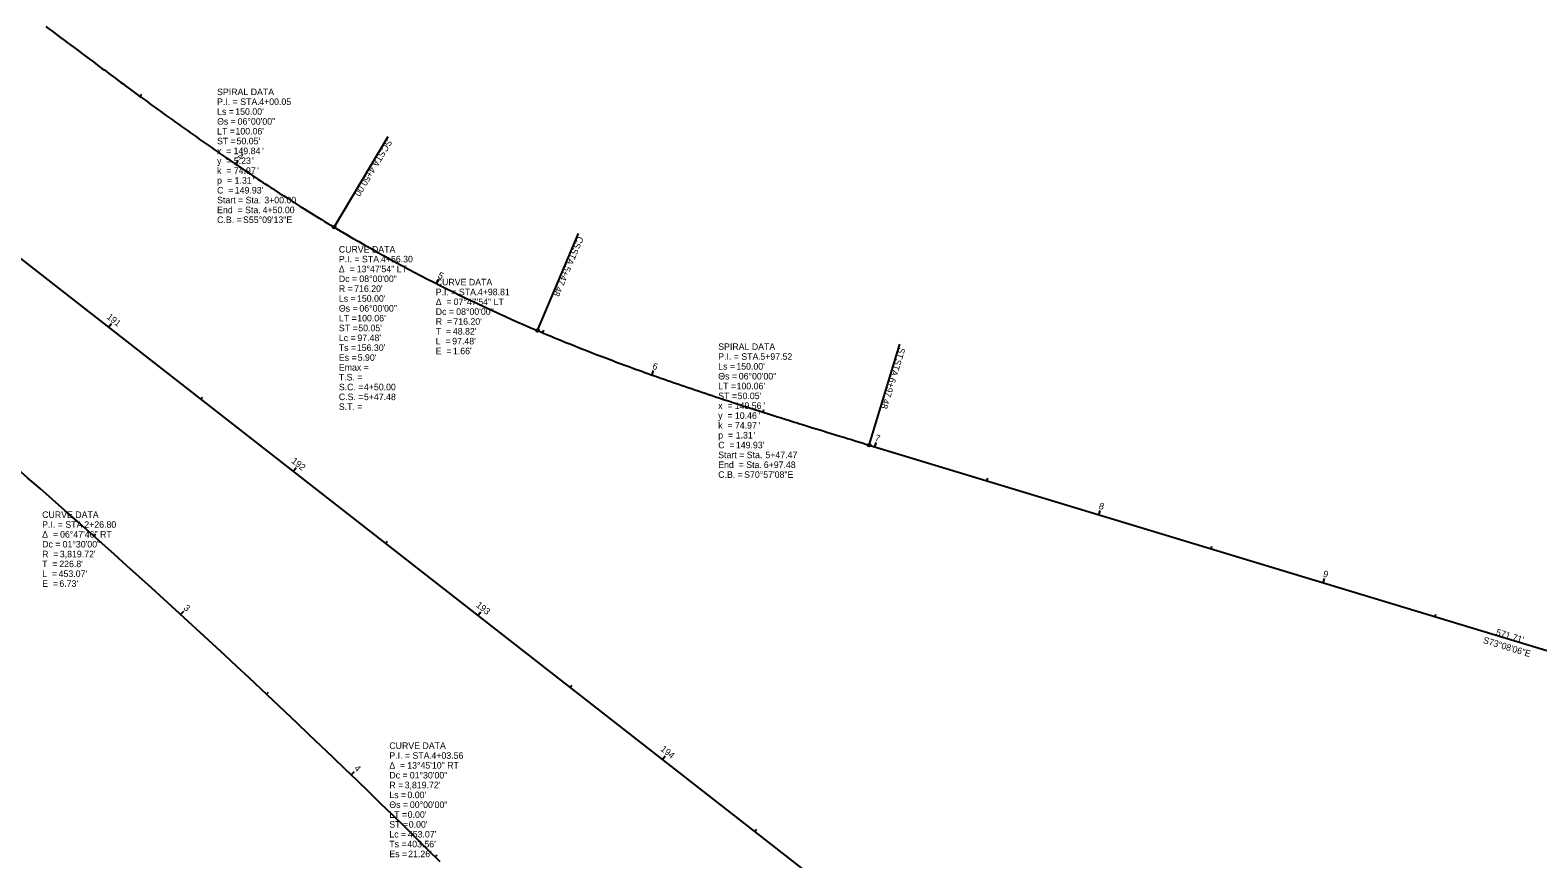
# Model space of a CAD drawing. Extents: x 1323137 to 1326838, y 458936 to 461644.
# Drawn here: x 1324445 to 1325088, y 460335 to 460688 of the extents above; entities that cross this region are included whole.
import ezdxf

# ---------------------------------------------------------------- set-up
doc = ezdxf.new("R2010")
doc.units = 0
for name, color, linetype in [('_CIVIL_CONSTRUCTION', 7, 'Continuous'), ('CM_Corridor_Final', 7, 'Continuous'), ('CM_Corridor_Range_Final', 7, 'Continuous'), ('Default', 7, 'Continuous'), ('DR_P_Ditch', 7, 'Continuous'), ('MD_P_Surface_Asphalt_Concrete_Intermediate_Course', 7, 'Continuous'), ('RD_P_GR_Rt', 7, 'Continuous'), ('SG_P_Wiring', 7, 'Continuous'), ('SN_P_Signs', 7, 'Continuous'), ('SN_X_Public', 7, 'Continuous'), ('UT_P_Electric_Cells', 7, 'Continuous'), ('UT_X_Electric_Cells', 7, 'Continuous')]:
    doc.layers.add(name, color=color, linetype=linetype)

msp = doc.modelspace()

# ---------------------------------------------------------------- linework, layer by layer
at = {"layer": '_CIVIL_CONSTRUCTION'}
for p, q in [((1324574.35, 460604.34), (1324597.43, 460642.98)), ((1324661.18, 460560.2), (1324678.8, 460601.61)), ((1324802.88, 460511.24), (1324815.94, 460554.31))]:
    msp.add_line(p, q, dxfattribs=at)
for centre in [(1324574.35, 460604.34), (1324661.18, 460560.2), (1324802.88, 460511.24)]:
    msp.add_circle(centre, 0.6, dxfattribs=at)
at = {"layer": 'CM_Corridor_Range_Final'}
for p, q in [((1324491.44, 460660.18), (1324492.15, 460661.14)), ((1324532.25, 460631.29), (1324533.37, 460632.95)), ((1324574.36, 460604.34), (1324574.97, 460605.37)), ((1324618.14, 460580.22), (1324619.05, 460582.01)), ((1324478.04, 460561.59), (1324479.27, 460563.17)), ((1324663.5, 460559.22), (1324663.97, 460560.32)), ((1324710.14, 460541.22), (1324710.81, 460543.1)), ((1324517.46, 460530.84), (1324518.2, 460531.78)), ((1324757.56, 460525.35), (1324757.92, 460526.49)), ((1324805.3, 460510.51), (1324805.88, 460512.42)), ((1324556.89, 460500.08), (1324558.12, 460501.66)), ((1324853.15, 460496), (1324853.5, 460497.15)), ((1324901, 460481.5), (1324901.58, 460483.41)), ((1324471.7, 460472.46), (1324472.49, 460473.35)), ((1324596.31, 460469.33), (1324597.05, 460470.28)), ((1324948.85, 460466.99), (1324949.2, 460468.14)), ((1324996.7, 460452.48), (1324997.28, 460454.4)), ((1324508.81, 460438.95), (1324510.16, 460440.42)), ((1324635.73, 460438.58), (1324636.96, 460440.15)), ((1325044.55, 460437.98), (1325044.89, 460439.13)), ((1324545.47, 460404.96), (1324546.29, 460405.83)), ((1324675.16, 460407.82), (1324675.89, 460408.77)), ((1324714.58, 460377.07), (1324715.81, 460378.65)), ((1324581.69, 460370.49), (1324583.08, 460371.93)), ((1324754, 460346.32), (1324754.74, 460347.26)), ((1324617.46, 460335.55), (1324618.3, 460336.4))]:
    msp.add_line(p, q, dxfattribs=at)
at = {"layer": 'Default'}
msp.add_line((1323137.63, 461607.2), (1324879.49, 460248.43), dxfattribs=at)
msp.add_arc((1324941.57, 461219.23), 716.2, 239.15381, 246.95218, dxfattribs=at)
msp.add_open_spline([(1324451.31, 460690.01), (1324454.64, 460687.51), (1324461.31, 460682.51), (1324474.66, 460672.54), (1324491.41, 460660.14), (1324511.67, 460645.5), (1324532.19, 460631.21), (1324549.56, 460619.71), (1324563.66, 460610.81), (1324570.77, 460606.48), (1324574.35, 460604.34)], degree=3, dxfattribs=at)
at = {"layer": 'MD_P_Surface_Asphalt_Concrete_Intermediate_Course'}
for p, q in [((1324574.35, 460604.34), (1324597.43, 460642.98)), ((1324661.18, 460560.2), (1324678.8, 460601.61)), ((1324802.88, 460511.24), (1324815.94, 460554.31))]:
    msp.add_line(p, q, dxfattribs=at)
for centre in [(1324574.35, 460604.34), (1324661.18, 460560.2), (1324802.88, 460511.24)]:
    msp.add_circle(centre, 0.6, dxfattribs=at)
at = {"layer": 'SN_P_Signs'}
for p, q in [((1323137.63, 461607.2), (1324879.49, 460248.43)), ((1324802.88, 460511.24), (1325350.01, 460345.38))]:
    msp.add_line(p, q, dxfattribs=at)
for centre, radius, start, end in [((1321930.37, 457620.81), 3819.72, 45.2472, 52.04331), ((1324941.57, 461219.23), 716.2, 239.15381, 246.95218)]:
    msp.add_arc(centre, radius, start, end, dxfattribs=at)
for points in [[(1324451.31, 460690.01), (1324454.64, 460687.51), (1324461.31, 460682.51), (1324474.66, 460672.54), (1324491.41, 460660.14), (1324511.67, 460645.5), (1324532.19, 460631.21), (1324549.56, 460619.71), (1324563.66, 460610.81), (1324570.77, 460606.48), (1324574.35, 460604.34)], [(1324661.18, 460560.2), (1324665.01, 460558.57), (1324672.71, 460555.38), (1324688.2, 460549.23), (1324707.73, 460541.98), (1324731.37, 460533.82), (1324755.14, 460526.07), (1324775.02, 460519.85), (1324790.95, 460514.94), (1324798.91, 460512.49), (1324802.9, 460511.27)]]:
    msp.add_open_spline(points, degree=3, dxfattribs=at)
at = {"layer": 'SN_X_Public'}
for p, q in [((1324532.25, 460631.29), (1324532.92, 460632.28)), ((1324618.14, 460580.22), (1324619.05, 460582.01)), ((1324478.04, 460561.59), (1324478.78, 460562.53)), ((1324710.14, 460541.22), (1324710.54, 460542.35)), ((1324805.3, 460510.51), (1324805.65, 460511.66)), ((1324556.89, 460500.08), (1324557.62, 460501.03)), ((1324901, 460481.5), (1324901.35, 460482.64)), ((1324996.7, 460452.48), (1324997.05, 460453.63)), ((1324508.81, 460438.95), (1324509.62, 460439.83)), ((1324635.73, 460438.58), (1324636.47, 460439.52)), ((1324714.58, 460377.07), (1324715.32, 460378.02)), ((1324581.69, 460370.49), (1324582.53, 460371.35))]:
    msp.add_line(p, q, dxfattribs=at)

# ---------------------------------------------------------------- texts
at = {"layer": '_CIVIL_CONSTRUCTION'}
for s, rotation, p in [('SC', 239.15381, (1324596.93, 460642.08)), (' STA. ', 239.15381, (1324594.7, 460638.34)), ('4+50.00', 239.15381, (1324589.92, 460630.34)), ('CS', 246.95192, (1324678.42, 460600.64)), (' STA. ', 246.95192, (1324676.72, 460596.63)), ('5+47.48', 246.95192, (1324673.07, 460588.05)), (' STA. ', 253.13488, (1324814.44, 460549.25)), ('ST', 253.13488, (1324815.64, 460553.18)), ('6+97.48', 253.13488, (1324811.74, 460540.33))]:
    msp.add_text(s, height=2.8, rotation=rotation, dxfattribs=at).set_placement(p)
at = {"layer": 'CM_Corridor_Final'}
for s, p in [('SPIRAL DATA', (1324524.4, 460660.69)), ('P.I. = STA. ', (1324524.4, 460656.49)), ('4+00.05', (1324542.39, 460656.49)), ('Θs = ', (1324524.4, 460648.09)), ('Ls = ', (1324524.4, 460652.29)), ("150.00'", (1324532.15, 460652.29)), ('06°00\'00"', (1324533.18, 460648.09)), ('LT = ', (1324524.4, 460643.89)), ("100.06'", (1324532.25, 460643.89)), ('x  = ', (1324524.4, 460635.49)), ('ST = ', (1324524.4, 460639.69)), ('149.84', (1324531.43, 460635.49)), ("50.05'", (1324532.7, 460639.69)), ("'", (1324543.69, 460635.49)), ('y  = ', (1324524.4, 460631.29)), ('5.23', (1324531.53, 460631.29)), ("'", (1324539.32, 460631.29)), ('p  = ', (1324524.4, 460622.89)), ('k  = ', (1324524.4, 460627.09)), ('74.97', (1324531.53, 460627.09)), ('1.31', (1324531.88, 460622.89)), ("'", (1324539.66, 460622.89)), ("'", (1324541.55, 460627.09)), ('C  = ', (1324524.4, 460618.69)), ("149.93'", (1324531.95, 460618.69)), ('Start = Sta. ', (1324524.4, 460614.49)), ('End  = Sta. ', (1324524.4, 460610.29)), ('4+50.00', (1324543.86, 460610.29)), ('3+00.00', (1324544.55, 460614.49)), ('C.B. = ', (1324524.4, 460606.09)), ('S55°09\'13"E', (1324535.47, 460606.09)), ('CURVE DATA', (1324576.39, 460593.48)), ('Δ  = ', (1324576.39, 460585.08)), ('P.I. = STA. ', (1324576.39, 460589.28)), ('13°47\'54" LT', (1324584.04, 460585.08)), ('4+56.30', (1324594.38, 460589.28)), ('Dc = ', (1324576.39, 460580.88)), ('R = ', (1324576.39, 460576.68)), ("716.20'", (1324582.93, 460576.68)), ('08°00\'00"', (1324585.14, 460580.88)), ('CURVE DATA', (1324617.77, 460579.47)), ('Ls = ', (1324576.39, 460572.48)), ("150.00'", (1324584.14, 460572.48)), ('Δ  = ', (1324617.77, 460571.07)), ('P.I. = STA. ', (1324617.77, 460575.27)), ('07°47\'54" LT', (1324625.41, 460571.07)), ('4+98.81', (1324635.76, 460575.27)), ('Θs = ', (1324576.39, 460568.28)), ('LT = ', (1324576.39, 460564.08)), ("100.06'", (1324584.24, 460564.08)), ('06°00\'00"', (1324585.17, 460568.28)), ('Dc = ', (1324617.77, 460566.87)), ('08°00\'00"', (1324626.51, 460566.87)), ('ST = ', (1324576.39, 460559.88)), ("50.05'", (1324584.69, 460559.88)), ('T  = ', (1324617.77, 460558.47)), ('R  = ', (1324617.77, 460562.67)), ("48.82'", (1324625.09, 460558.47)), ("716.20'", (1324625.3, 460562.67)), ('Ts = ', (1324576.39, 460551.48)), ('Lc = ', (1324576.39, 460555.68)), ("156.30'", (1324584.08, 460551.48)), ("97.48'", (1324584.31, 460555.68)), ('L  = ', (1324617.77, 460554.27)), ("97.48'", (1324624.8, 460554.27)), ('SPIRAL DATA', (1324738.4, 460551.9)), ('Es = ', (1324576.39, 460547.28)), ("5.90'", (1324584.44, 460547.28)), ('E  = ', (1324617.77, 460550.07)), ("1.66'", (1324625.11, 460550.07)), ('P.I. = STA. ', (1324738.4, 460547.7)), ('5+97.52', (1324756.39, 460547.7)), ('T.S. = ', (1324576.39, 460538.88)), ('Emax = ', (1324576.39, 460543.08)), ('Θs = ', (1324738.4, 460539.3)), ('Ls = ', (1324738.4, 460543.5)), ("150.00'", (1324746.14, 460543.5)), ('06°00\'00"', (1324747.18, 460539.3)), ('S.C. = ', (1324576.39, 460534.68)), ('4+50.00', (1324587.1, 460534.68)), ('LT = ', (1324738.4, 460535.1)), ("100.06'", (1324746.25, 460535.1)), ('S.T. = ', (1324576.39, 460526.28)), ('C.S. = ', (1324576.39, 460530.48)), ('5+47.48', (1324587.1, 460530.48)), ('x  = ', (1324738.4, 460526.7)), ('ST = ', (1324738.4, 460530.9)), ('149.56', (1324745.43, 460526.7)), ("50.05'", (1324746.7, 460530.9)), ("'", (1324757.68, 460526.7)), ('y  = ', (1324738.4, 460522.5)), ('10.46', (1324745.53, 460522.5)), ("'", (1324755.55, 460522.5)), ('p  = ', (1324738.4, 460514.1)), ('k  = ', (1324738.4, 460518.3)), ('74.97', (1324745.53, 460518.3)), ('1.31', (1324745.88, 460514.1)), ("'", (1324753.66, 460514.1)), ("'", (1324755.55, 460518.3)), ('Start = Sta. ', (1324738.4, 460505.7)), ('C  = ', (1324738.4, 460509.9)), ("149.93'", (1324745.95, 460509.9)), ('5+47.47', (1324758.55, 460505.7)), ('End  = Sta. ', (1324738.4, 460501.5)), ('6+97.48', (1324757.86, 460501.5)), ('C.B. = ', (1324738.4, 460497.3)), ('S70°57\'08"E', (1324749.47, 460497.3)), ('CURVE DATA', (1324449.69, 460480.17)), ('P.I. = STA. ', (1324449.69, 460475.97)), ('2+26.80', (1324467.69, 460475.97)), ('Δ  = ', (1324449.69, 460471.77)), ('Dc = ', (1324449.69, 460467.57)), ('06°47\'46" RT', (1324457.34, 460471.77)), ('01°30\'00"', (1324458.44, 460467.57)), ('R  = ', (1324449.69, 460463.37)), ("3,819.72'", (1324457.23, 460463.37)), ('T  = ', (1324449.69, 460459.17)), ('L  = ', (1324449.69, 460454.97)), ("453.07'", (1324456.73, 460454.97)), ("226.8'", (1324457.01, 460459.17)), ('E  = ', (1324449.69, 460450.77)), ("6.73'", (1324457.04, 460450.77)), ('CURVE DATA', (1324597.95, 460381.55)), ('P.I. = STA. ', (1324597.95, 460377.35)), ('4+03.56', (1324615.94, 460377.35)), ('Δ  = ', (1324597.95, 460373.15)), ('13°45\'10" RT', (1324605.59, 460373.15)), ('Dc = ', (1324597.95, 460368.95)), ('R = ', (1324597.95, 460364.75)), ("3,819.72'", (1324604.49, 460364.75)), ('01°30\'00"', (1324606.69, 460368.95)), ('Ls = ', (1324597.95, 460360.55)), ("0.00'", (1324605.69, 460360.55)), ('Θs = ', (1324597.95, 460356.35)), ('LT = ', (1324597.95, 460352.15)), ("0.00'", (1324605.79, 460352.15)), ('00°00\'00"', (1324606.73, 460356.35)), ('ST = ', (1324597.95, 460347.95)), ("0.00'", (1324606.25, 460347.95)), ('Ts = ', (1324597.95, 460339.55)), ('Lc = ', (1324597.95, 460343.75)), ("403.56'", (1324605.63, 460339.55)), ("453.07'", (1324605.86, 460343.75)), ('Es = ', (1324597.95, 460335.35)), ("21.26'", (1324606, 460335.35))]:
    msp.add_text(s, height=2.8, dxfattribs=at).set_placement(p)
at = {"layer": 'CM_Corridor_Range_Final'}
for s, rotation, p in [('4', 325.82072, (1324532.79, 460633.95)), ('5', 333.15414, (1324618.4, 460582.89)), ('191', 322.04331, (1324477.03, 460565.54)), ('6', 340.41816, (1324710.02, 460543.92)), ('7', 343.13488, (1324805.06, 460513.19)), ('192', 322.04331, (1324555.89, 460504.03)), ('8', 343.13488, (1324900.75, 460484.18)), ('9', 343.13488, (1324996.47, 460455.16)), ('193', 322.04331, (1324634.75, 460442.51)), ('3', 317.54331, (1324509.78, 460441.44)), ('194', 322.04331, (1324713.53, 460381.06)), ('4', 316.04331, (1324582.68, 460373.01))]:
    msp.add_text(s, height=2.8, rotation=rotation, dxfattribs=at).set_placement(p)
at = {"layer": 'DR_P_Ditch'}
msp.add_text("571.71'", height=2.8, rotation=343.13488, dxfattribs=at).set_placement((1325070.29, 460430.21))
at = {"layer": 'MD_P_Surface_Asphalt_Concrete_Intermediate_Course'}
for s, rotation, p in [('SC', 239.15381, (1324596.93, 460642.08)), (' STA. ', 239.15381, (1324594.7, 460638.34)), ('4+50.00', 239.15381, (1324589.92, 460630.34)), ('CS', 246.95192, (1324678.42, 460600.64)), (' STA. ', 246.95192, (1324676.72, 460596.63)), ('5+47.48', 246.95192, (1324673.07, 460588.05)), (' STA. ', 253.13488, (1324814.44, 460549.25)), ('ST', 253.13488, (1324815.64, 460553.18)), ('6+97.48', 253.13488, (1324811.74, 460540.33))]:
    msp.add_text(s, height=2.8, rotation=rotation, dxfattribs=at).set_placement(p)
at = {"layer": 'RD_P_GR_Rt'}
msp.add_text('S73°08\'06"E', height=2.8, rotation=343.13488, dxfattribs=at).set_placement((1325064.8, 460426.82))
at = {"layer": 'SG_P_Wiring'}
msp.add_text('S73°08\'06"E', height=2.8, rotation=343.13488, dxfattribs=at).set_placement((1325064.8, 460426.82))
at = {"layer": 'SN_X_Public'}
msp.add_text('5', height=2.8, rotation=333.15414, dxfattribs=at).set_placement((1324618.4, 460582.89))
at = {"layer": 'UT_P_Electric_Cells'}
for s, p in [('SPIRAL DATA', (1324524.4, 460660.69)), ('P.I. = STA. ', (1324524.4, 460656.49)), ('4+00.05', (1324542.39, 460656.49)), ('Θs = ', (1324524.4, 460648.09)), ('Ls = ', (1324524.4, 460652.29)), ("150.00'", (1324532.15, 460652.29)), ('06°00\'00"', (1324533.18, 460648.09)), ('LT = ', (1324524.4, 460643.89)), ("100.06'", (1324532.25, 460643.89)), ('x  = ', (1324524.4, 460635.49)), ('ST = ', (1324524.4, 460639.69)), ('149.84', (1324531.43, 460635.49)), ("50.05'", (1324532.7, 460639.69)), ("'", (1324543.69, 460635.49)), ('y  = ', (1324524.4, 460631.29)), ('5.23', (1324531.53, 460631.29)), ("'", (1324539.32, 460631.29)), ('p  = ', (1324524.4, 460622.89)), ('k  = ', (1324524.4, 460627.09)), ('74.97', (1324531.53, 460627.09)), ('1.31', (1324531.88, 460622.89)), ("'", (1324539.66, 460622.89)), ("'", (1324541.55, 460627.09)), ('C  = ', (1324524.4, 460618.69)), ("149.93'", (1324531.95, 460618.69)), ('Start = Sta. ', (1324524.4, 460614.49)), ('End  = Sta. ', (1324524.4, 460610.29)), ('4+50.00', (1324543.86, 460610.29)), ('3+00.00', (1324544.55, 460614.49)), ('C.B. = ', (1324524.4, 460606.09)), ('S55°09\'13"E', (1324535.47, 460606.09)), ('CURVE DATA', (1324576.39, 460593.48)), ('Δ  = ', (1324576.39, 460585.08)), ('P.I. = STA. ', (1324576.39, 460589.28)), ('13°47\'54" LT', (1324584.04, 460585.08)), ('4+56.30', (1324594.38, 460589.28)), ('Dc = ', (1324576.39, 460580.88)), ('R = ', (1324576.39, 460576.68)), ("716.20'", (1324582.93, 460576.68)), ('08°00\'00"', (1324585.14, 460580.88)), ('CURVE DATA', (1324617.77, 460579.47)), ('Ls = ', (1324576.39, 460572.48)), ("150.00'", (1324584.14, 460572.48)), ('Δ  = ', (1324617.77, 460571.07)), ('P.I. = STA. ', (1324617.77, 460575.27)), ('07°47\'54" LT', (1324625.41, 460571.07)), ('4+98.81', (1324635.76, 460575.27)), ('Θs = ', (1324576.39, 460568.28)), ('LT = ', (1324576.39, 460564.08)), ("100.06'", (1324584.24, 460564.08)), ('06°00\'00"', (1324585.17, 460568.28)), ('Dc = ', (1324617.77, 460566.87)), ('08°00\'00"', (1324626.51, 460566.87)), ('ST = ', (1324576.39, 460559.88)), ("50.05'", (1324584.69, 460559.88)), ('T  = ', (1324617.77, 460558.47)), ('R  = ', (1324617.77, 460562.67)), ("48.82'", (1324625.09, 460558.47)), ("716.20'", (1324625.3, 460562.67)), ('Ts = ', (1324576.39, 460551.48)), ('Lc = ', (1324576.39, 460555.68)), ("156.30'", (1324584.08, 460551.48)), ("97.48'", (1324584.31, 460555.68)), ('L  = ', (1324617.77, 460554.27)), ("97.48'", (1324624.8, 460554.27)), ('SPIRAL DATA', (1324738.4, 460551.9)), ('Es = ', (1324576.39, 460547.28)), ("5.90'", (1324584.44, 460547.28)), ('E  = ', (1324617.77, 460550.07)), ("1.66'", (1324625.11, 460550.07)), ('P.I. = STA. ', (1324738.4, 460547.7)), ('5+97.52', (1324756.39, 460547.7)), ('T.S. = ', (1324576.39, 460538.88)), ('Emax = ', (1324576.39, 460543.08)), ('Θs = ', (1324738.4, 460539.3)), ('Ls = ', (1324738.4, 460543.5)), ("150.00'", (1324746.14, 460543.5)), ('06°00\'00"', (1324747.18, 460539.3)), ('S.C. = ', (1324576.39, 460534.68)), ('4+50.00', (1324587.1, 460534.68)), ('LT = ', (1324738.4, 460535.1)), ("100.06'", (1324746.25, 460535.1)), ('S.T. = ', (1324576.39, 460526.28)), ('C.S. = ', (1324576.39, 460530.48)), ('5+47.48', (1324587.1, 460530.48)), ('x  = ', (1324738.4, 460526.7)), ('ST = ', (1324738.4, 460530.9)), ('149.56', (1324745.43, 460526.7)), ("50.05'", (1324746.7, 460530.9)), ("'", (1324757.68, 460526.7)), ('y  = ', (1324738.4, 460522.5)), ('10.46', (1324745.53, 460522.5)), ("'", (1324755.55, 460522.5)), ('p  = ', (1324738.4, 460514.1)), ('k  = ', (1324738.4, 460518.3)), ('74.97', (1324745.53, 460518.3)), ('1.31', (1324745.88, 460514.1)), ("'", (1324753.66, 460514.1)), ("'", (1324755.55, 460518.3)), ('Start = Sta. ', (1324738.4, 460505.7)), ('C  = ', (1324738.4, 460509.9)), ("149.93'", (1324745.95, 460509.9)), ('5+47.47', (1324758.55, 460505.7)), ('End  = Sta. ', (1324738.4, 460501.5)), ('6+97.48', (1324757.86, 460501.5)), ('C.B. = ', (1324738.4, 460497.3)), ('S70°57\'08"E', (1324749.47, 460497.3)), ('CURVE DATA', (1324449.69, 460480.17)), ('P.I. = STA. ', (1324449.69, 460475.97)), ('2+26.80', (1324467.69, 460475.97)), ('Δ  = ', (1324449.69, 460471.77)), ('Dc = ', (1324449.69, 460467.57)), ('06°47\'46" RT', (1324457.34, 460471.77)), ('01°30\'00"', (1324458.44, 460467.57)), ('R  = ', (1324449.69, 460463.37)), ("3,819.72'", (1324457.23, 460463.37)), ('T  = ', (1324449.69, 460459.17)), ('L  = ', (1324449.69, 460454.97)), ("453.07'", (1324456.73, 460454.97)), ("226.8'", (1324457.01, 460459.17)), ('E  = ', (1324449.69, 460450.77)), ("6.73'", (1324457.04, 460450.77)), ('CURVE DATA', (1324597.95, 460381.55)), ('P.I. = STA. ', (1324597.95, 460377.35)), ('4+03.56', (1324615.94, 460377.35)), ('Δ  = ', (1324597.95, 460373.15)), ('13°45\'10" RT', (1324605.59, 460373.15)), ('Dc = ', (1324597.95, 460368.95)), ('R = ', (1324597.95, 460364.75)), ("3,819.72'", (1324604.49, 460364.75)), ('01°30\'00"', (1324606.69, 460368.95)), ('Ls = ', (1324597.95, 460360.55)), ("0.00'", (1324605.69, 460360.55)), ('Θs = ', (1324597.95, 460356.35)), ('LT = ', (1324597.95, 460352.15)), ("0.00'", (1324605.79, 460352.15)), ('00°00\'00"', (1324606.73, 460356.35)), ('ST = ', (1324597.95, 460347.95)), ("0.00'", (1324606.25, 460347.95)), ('Ts = ', (1324597.95, 460339.55)), ('Lc = ', (1324597.95, 460343.75)), ("403.56'", (1324605.63, 460339.55)), ("453.07'", (1324605.86, 460343.75)), ('Es = ', (1324597.95, 460335.35)), ("21.26'", (1324606, 460335.35))]:
    msp.add_text(s, height=2.8, dxfattribs=at).set_placement(p)
at = {"layer": 'UT_X_Electric_Cells'}
msp.add_text("571.71'", height=2.8, rotation=343.13488, dxfattribs=at).set_placement((1325070.29, 460430.21))

doc.saveas('drawing.dxf')
